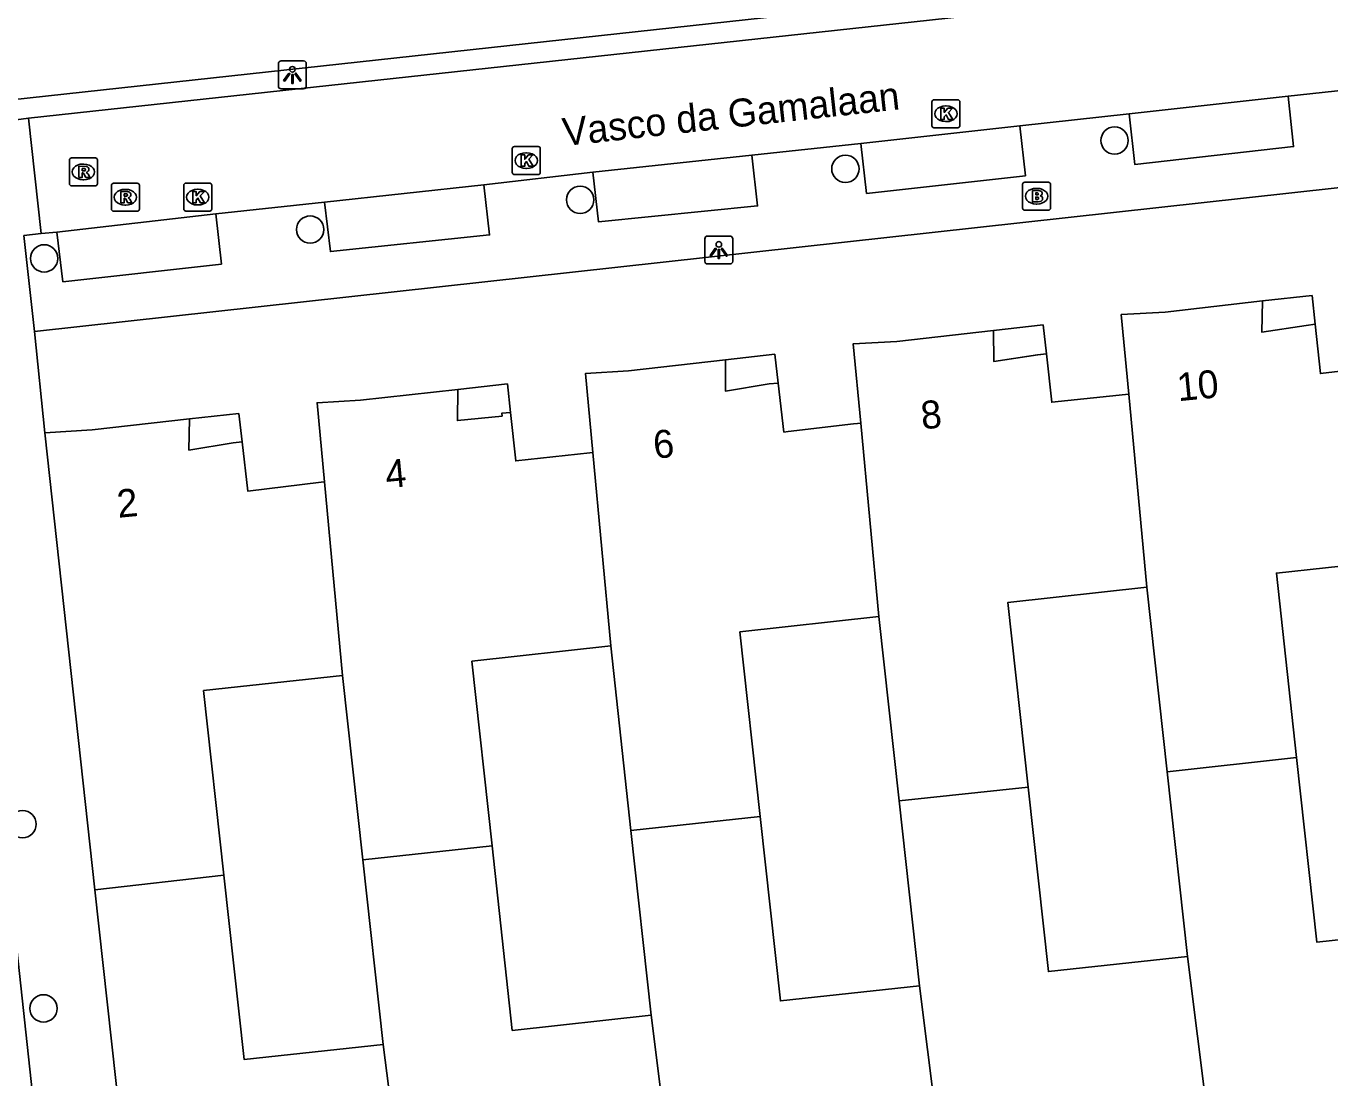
# Model space of a CAD drawing. Extents: x 161253 to 161848, y 384872 to 385383.
# Drawn here: x 161347.65 to 161394.3, y 385074.55 to 385112.17 of the extents above; entities that cross this region are included whole.
import ezdxf

# ---------------------------------------------------------------- set-up
doc = ezdxf.new("R2010")
doc.units = 0
for name, color, linetype in [('IMGEO_Boom', 7, 'Continuous'), ('IMGEO_Brandkraan', 7, 'Continuous'), ('IMGEO_Kolk', 7, 'Continuous'), ('IMGEO_Lichtpunt', 7, 'Continuous'), ('IMGEO_Openbare_ruimte_label', 7, 'Continuous'), ('IMGEO_Pand', 7, 'Continuous'), ('IMGEO_Pand_nummerreeks', 7, 'Continuous'), ('IMGEO_Pand_overbouw', 7, 'Continuous'), ('IMGEO_Rijbaan_lokaal_open', 7, 'Continuous'), ('IMGEO_Rioolput', 7, 'Continuous'), ('IMGEO_Voetpad_open', 7, 'Continuous')]:
    doc.layers.add(name, color=color, linetype=linetype)

msp = doc.modelspace()

# ---------------------------------------------------------------- linework, layer by layer
at = {"layer": 'IMGEO_Boom'}
for centre in [(161386.594, 385108.08), (161376.963, 385107.067), (161367.474, 385105.962), (161357.815, 385104.894), (161348.299, 385103.866), (161347.527, 385083.626), (161348.275, 385077.04)]:
    msp.add_circle(centre, 0.489, dxfattribs=at)
at = {"layer": 'IMGEO_Brandkraan'}
for p, q in [((161383.303, 385105.663), (161383.303, 385106.515)), ((161383.378, 385106.589), (161384.23, 385106.589)), ((161384.304, 385106.515), (161384.304, 385105.663)), ((161383.791, 385106.369), (161383.816, 385106.369)), ((161384.23, 385105.589), (161383.378, 385105.589)), ((161383.814, 385105.809), (161383.789, 385105.809))]:
    msp.add_line(p, q, dxfattribs=at)
for points in [[(161383.303, 385105.663), (161383.303, 385106.515)], [(161383.378, 385106.589), (161384.23, 385106.589)], [(161384.304, 385106.515), (161384.304, 385105.663)], [(161383.651, 385106.289), (161383.651, 385105.889), (161383.864, 385105.889)], [(161383.882, 385106.289), (161383.651, 385106.289)], [(161383.83, 385106.208), (161383.776, 385106.208), (161383.776, 385106.132)], [(161383.776, 385106.132), (161383.829, 385106.132)], [(161383.838, 385106.056), (161383.776, 385106.056), (161383.776, 385105.975)], [(161384.23, 385105.589), (161383.378, 385105.589)], [(161383.776, 385105.975), (161383.838, 385105.975)]]:
    msp.add_lwpolyline(points, dxfattribs=at)
for centre, radius, start, end in [((161383.38, 385106.513), 0.0765, 91.552, 178.448), ((161383.38, 385106.513), 0.0765, 91.552, 178.448), ((161384.228, 385106.513), 0.0765, 1.552, 88.448), ((161384.228, 385106.513), 0.0765, 1.552, 88.448), ((161383.831, 385106.17), 0.0379, 267.8285, 90.9355), ((161383.839, 385106.015), 0.0404, 269.8759, 90.5077), ((161383.886, 385106.144), 0.145, 59.4692, 91.5367), ((161383.911, 385106.191), 0.0922, 285.5137, 58.1501), ((161383.916, 385105.999), 0.105, 301.3115, 78.989), ((161383.38, 385105.665), 0.0765, 181.552, 268.448), ((161383.38, 385105.665), 0.0765, 181.552, 268.448), ((161383.87, 385106.14), 0.251, 268.6676, 293.5347), ((161384.228, 385105.665), 0.0765, 271.552, 358.448), ((161384.228, 385105.665), 0.0765, 271.552, 358.448)]:
    msp.add_arc(centre, radius, start, end, dxfattribs=at)
for centre, major_axis, ratio, start_param, end_param in [((161383.79, 385106.089), (-0.387, 0.002), 0.722429, 4.712389, 7.853982), ((161383.815, 385106.089), (-0.39, 0.002), 0.717154, 1.570796, 4.712389)]:
    msp.add_ellipse(centre, major_axis=major_axis, ratio=ratio, start_param=start_param, end_param=end_param, dxfattribs=at)
at = {"layer": 'IMGEO_Kolk'}
for p, q in [((161380.058, 385108.61), (161380.058, 385109.462)), ((161380.133, 385109.536), (161380.985, 385109.536)), ((161380.546, 385109.316), (161380.571, 385109.316)), ((161381.059, 385109.462), (161381.059, 385108.61)), ((161380.985, 385108.536), (161380.133, 385108.536)), ((161380.569, 385108.756), (161380.544, 385108.756)), ((161365.048, 385106.937), (161365.048, 385107.789)), ((161365.123, 385107.863), (161365.975, 385107.863)), ((161365.536, 385107.643), (161365.561, 385107.643)), ((161366.049, 385107.789), (161366.049, 385106.937)), ((161365.559, 385107.083), (161365.534, 385107.083)), ((161353.371, 385106.555), (161354.223, 385106.555)), ((161365.975, 385106.863), (161365.123, 385106.863)), ((161353.296, 385105.629), (161353.296, 385106.481)), ((161353.784, 385106.335), (161353.809, 385106.335)), ((161354.297, 385106.481), (161354.297, 385105.629)), ((161354.223, 385105.555), (161353.371, 385105.555)), ((161353.807, 385105.775), (161353.782, 385105.775))]:
    msp.add_line(p, q, dxfattribs=at)
for points in [[(161380.058, 385108.61), (161380.058, 385109.462)], [(161380.133, 385109.536), (161380.985, 385109.536)], [(161381.059, 385109.462), (161381.059, 385108.61)], [(161380.379, 385109.236), (161380.502, 385109.236), (161380.502, 385109.085), (161380.632, 385109.236), (161380.796, 385109.236), (161380.65, 385109.085), (161380.803, 385108.836), (161380.651, 385108.836), (161380.566, 385109), (161380.502, 385108.933), (161380.502, 385108.836), (161380.379, 385108.836), (161380.379, 385109.236)], [(161380.985, 385108.536), (161380.133, 385108.536)], [(161365.048, 385106.937), (161365.048, 385107.789)], [(161365.123, 385107.863), (161365.975, 385107.863)], [(161365.369, 385107.563), (161365.492, 385107.563), (161365.492, 385107.412), (161365.622, 385107.563), (161365.786, 385107.563), (161365.64, 385107.412), (161365.793, 385107.163), (161365.641, 385107.163), (161365.556, 385107.327), (161365.492, 385107.26), (161365.492, 385107.163), (161365.369, 385107.163), (161365.369, 385107.563)], [(161366.049, 385107.789), (161366.049, 385106.937)], [(161353.371, 385106.555), (161354.223, 385106.555)], [(161365.975, 385106.863), (161365.123, 385106.863)], [(161353.296, 385105.629), (161353.296, 385106.481)], [(161353.617, 385106.255), (161353.74, 385106.255), (161353.74, 385106.104), (161353.87, 385106.255), (161354.034, 385106.255), (161353.888, 385106.104), (161354.041, 385105.855), (161353.889, 385105.855), (161353.804, 385106.019), (161353.74, 385105.952), (161353.74, 385105.855), (161353.617, 385105.855), (161353.617, 385106.255)], [(161354.297, 385106.481), (161354.297, 385105.629)], [(161354.223, 385105.555), (161353.371, 385105.555)]]:
    msp.add_lwpolyline(points, dxfattribs=at)
for centre, start, end in [((161380.135, 385109.46), 91.552, 178.448), ((161380.135, 385109.46), 91.552, 178.448), ((161380.983, 385109.46), 1.552, 88.448), ((161380.983, 385109.46), 1.552, 88.448), ((161380.135, 385108.612), 181.552, 268.448), ((161380.135, 385108.612), 181.552, 268.448), ((161380.983, 385108.612), 271.552, 358.448), ((161380.983, 385108.612), 271.552, 358.448), ((161365.125, 385107.787), 91.552, 178.448), ((161365.125, 385107.787), 91.552, 178.448), ((161365.973, 385107.787), 1.552, 88.448), ((161365.973, 385107.787), 1.552, 88.448), ((161353.373, 385106.479), 91.552, 178.448), ((161353.373, 385106.479), 91.552, 178.448), ((161354.221, 385106.479), 1.552, 88.448), ((161354.221, 385106.479), 1.552, 88.448), ((161365.125, 385106.939), 181.552, 268.448), ((161365.125, 385106.939), 181.552, 268.448), ((161365.973, 385106.939), 271.552, 358.448), ((161365.973, 385106.939), 271.552, 358.448), ((161353.373, 385105.631), 181.552, 268.448), ((161353.373, 385105.631), 181.552, 268.448), ((161354.221, 385105.631), 271.552, 358.448), ((161354.221, 385105.631), 271.552, 358.448)]:
    msp.add_arc(centre, 0.0765, start, end, dxfattribs=at)
for centre, major_axis, ratio, start_param, end_param in [((161380.545, 385109.036), (-0.387, 0.002), 0.722429, 4.712389, 7.853982), ((161380.57, 385109.036), (-0.39, 0.002), 0.717154, 1.570796, 4.712389), ((161365.535, 385107.363), (-0.387, 0.002), 0.722429, 4.712389, 7.853982), ((161365.56, 385107.363), (-0.39, 0.002), 0.717154, 1.570796, 4.712389), ((161353.783, 385106.055), (-0.387, 0.002), 0.722429, 4.712389, 7.853982), ((161353.808, 385106.055), (-0.39, 0.002), 0.717154, 1.570796, 4.712389)]:
    msp.add_ellipse(centre, major_axis=major_axis, ratio=ratio, start_param=start_param, end_param=end_param, dxfattribs=at)
at = {"layer": 'IMGEO_Lichtpunt'}
for p, q in [((161356.682, 385110.83), (161356.682, 385110.023)), ((161356.682, 385110.83), (161356.682, 385110.023)), ((161357.584, 385110.925), (161356.776, 385110.925)), ((161357.584, 385110.925), (161356.776, 385110.925)), ((161357.678, 385110.023), (161357.678, 385110.83)), ((161357.678, 385110.023), (161357.678, 385110.83)), ((161356.776, 385109.929), (161357.584, 385109.929)), ((161356.776, 385109.929), (161357.584, 385109.929)), ((161372.838, 385104.662), (161372.03, 385104.662)), ((161372.838, 385104.662), (161372.03, 385104.662)), ((161371.936, 385104.567), (161371.936, 385103.76)), ((161371.936, 385104.567), (161371.936, 385103.76)), ((161372.932, 385103.76), (161372.932, 385104.567)), ((161372.932, 385103.76), (161372.932, 385104.567)), ((161372.03, 385103.666), (161372.838, 385103.666)), ((161372.03, 385103.666), (161372.838, 385103.666))]:
    msp.add_line(p, q, dxfattribs=at)
for points in [[(161357.056, 385110.494), (161357.095, 385110.466), (161356.907, 385110.204), (161356.869, 385110.231), (161357.056, 385110.494)], [(161357.158, 385110.446), (161357.205, 385110.446), (161357.205, 385110.124), (161357.158, 385110.124), (161357.158, 385110.446)], [(161357.268, 385110.466), (161357.306, 385110.493), (161357.493, 385110.231), (161357.454, 385110.203), (161357.268, 385110.466)], [(161372.31, 385104.231), (161372.349, 385104.203), (161372.161, 385103.941), (161372.123, 385103.968), (161372.31, 385104.231)], [(161372.412, 385104.183), (161372.459, 385104.183), (161372.459, 385103.861), (161372.412, 385103.861), (161372.412, 385104.183)], [(161372.522, 385104.203), (161372.56, 385104.23), (161372.747, 385103.968), (161372.708, 385103.94), (161372.522, 385104.203)]]:
    msp.add_lwpolyline(points, dxfattribs=at)
for centre in [(161357.181, 385110.628), (161372.435, 385104.365)]:
    msp.add_circle(centre, 0.0994, dxfattribs=at)
for centre, start, end in [((161356.776, 385110.83), 90, 180), ((161356.776, 385110.83), 90, 180), ((161357.584, 385110.83), 0, 90), ((161357.584, 385110.83), 0, 90), ((161356.776, 385110.023), 180, 270), ((161356.776, 385110.023), 180, 270), ((161357.584, 385110.023), 270, 0), ((161357.584, 385110.023), 270, 360), ((161372.03, 385104.567), 90, 180), ((161372.03, 385104.567), 90, 180), ((161372.838, 385104.567), 0, 90), ((161372.838, 385104.567), 0, 90), ((161372.03, 385103.76), 180, 270), ((161372.03, 385103.76), 180, 270), ((161372.838, 385103.76), 270, 0), ((161372.838, 385103.76), 270, 360)]:
    msp.add_arc(centre, 0.0946, start, end, dxfattribs=at)
at = {"layer": 'IMGEO_Pand'}
for points in [[(161396.893, 385100.095), (161393.957, 385099.746), (161393.768, 385101.507), (161393.446, 385101.462), (161391.863, 385101.222), (161391.885, 385102.341), (161388.402, 385101.946), (161386.833, 385101.856), (161387.099, 385099.013)], [(161377.511, 385097.974), (161377.246, 385100.811), (161378.806, 385100.893), (161382.257, 385101.285), (161382.274, 385100.174), (161383.835, 385100.418), (161384.156, 385100.449), (161384.347, 385098.716), (161386.986, 385099.001), (161387.099, 385099.013)], [(161377.511, 385097.974), (161377.398, 385097.961), (161377.249, 385097.943), (161374.919, 385097.667), (161374.763, 385097.649), (161374.563, 385099.398), (161374.239, 385099.377), (161372.674, 385099.12), (161372.675, 385100.219), (161372.675, 385100.238), (161369.2, 385099.839), (161367.668, 385099.753), (161367.93, 385096.926)], [(161367.93, 385096.926), (161367.817, 385096.913), (161365.171, 385096.619), (161364.982, 385098.356), (161364.67, 385098.325), (161364.68, 385098.223), (161363.085, 385098.066), (161363.102, 385099.18), (161359.617, 385098.791), (161358.064, 385098.701), (161358.329, 385095.868)], [(161387.099, 385099.013), (161387.745, 385092.1)], [(161358.329, 385095.868), (161358.216, 385095.855), (161355.582, 385095.542), (161355.384, 385097.3), (161355.064, 385097.262), (161353.479, 385097.007), (161353.505, 385098.125), (161350.02, 385097.735), (161348.324, 385097.628)], [(161348.324, 385097.628), (161350.119, 385081.284)], [(161378.158, 385091.05), (161377.511, 385097.974)], [(161367.93, 385096.926), (161368.572, 385090.002)], [(161358.329, 385095.868), (161358.976, 385088.951)], [(161393.106, 385086.007), (161392.383, 385092.607), (161397.643, 385093.177)], [(161383.499, 385084.956), (161382.774, 385091.556), (161387.745, 385092.1)], [(161387.745, 385092.1), (161388.471, 385085.497)], [(161373.914, 385083.906), (161373.188, 385090.506), (161378.158, 385091.05)], [(161378.158, 385091.05), (161378.883, 385084.458)], [(161364.324, 385082.857), (161363.603, 385089.458), (161368.572, 385090.002)], [(161368.572, 385090.002), (161369.294, 385083.399)], [(161354.733, 385081.808), (161354.006, 385088.408), (161358.976, 385088.951)], [(161358.976, 385088.951), (161359.704, 385082.348)], [(161388.471, 385085.497), (161393.106, 385086.007)], [(161399.089, 385079.976), (161393.83, 385079.404), (161393.106, 385086.007)], [(161388.471, 385085.497), (161389.196, 385078.897)], [(161383.499, 385084.956), (161378.883, 385084.458)], [(161389.196, 385078.897), (161384.225, 385078.353), (161383.499, 385084.956)], [(161378.883, 385084.458), (161379.61, 385077.848)], [(161369.294, 385083.399), (161373.914, 385083.906)], [(161379.61, 385077.848), (161374.64, 385077.304), (161373.914, 385083.906)], [(161369.294, 385083.399), (161370.015, 385076.798)], [(161364.324, 385082.857), (161359.704, 385082.348)], [(161370.015, 385076.798), (161365.046, 385076.254), (161364.324, 385082.857)], [(161359.704, 385082.348), (161360.431, 385075.749)], [(161354.733, 385081.808), (161350.119, 385081.284)], [(161360.431, 385075.749), (161355.46, 385075.205), (161354.733, 385081.808)], [(161350.119, 385081.284), (161351.915, 385064.931)], [(161390.289, 385070.246), (161389.196, 385078.897)], [(161379.61, 385077.848), (161380.486, 385070.921)], [(161371.106, 385068.129), (161370.015, 385076.798)], [(161361.306, 385068.843), (161360.431, 385075.749)]]:
    msp.add_lwpolyline(points, dxfattribs=at)
at = {"layer": 'IMGEO_Pand_overbouw'}
for points in [[(161393.657, 385102.542), (161391.885, 385102.341), (161391.863, 385101.222), (161393.446, 385101.462), (161393.768, 385101.507)], [(161384.041, 385101.488), (161382.257, 385101.285), (161382.274, 385100.174), (161383.849, 385100.419), (161384.156, 385100.449)], [(161374.444, 385100.441), (161372.675, 385100.238), (161372.674, 385099.12), (161374.239, 385099.377), (161374.563, 385099.398)], [(161364.871, 385099.377), (161363.102, 385099.18), (161363.085, 385098.066), (161364.68, 385098.223), (161364.67, 385098.325), (161364.982, 385098.356)], [(161355.269, 385098.322), (161353.505, 385098.125), (161353.479, 385097.007), (161355.064, 385097.262), (161355.384, 385097.3)]]:
    msp.add_lwpolyline(points, close=True, dxfattribs=at)
at = {"layer": 'IMGEO_Rijbaan_lokaal_open'}
for points in [[(161347.74, 385108.882), (161395.323, 385114.062)], [(161395.787, 385109.99), (161392.803, 385109.668)], [(161387.116, 385109.034), (161392.803, 385109.668)], [(161347.116, 385108.799), (161347.74, 385108.882)], [(161347.74, 385108.882), (161348.197, 385104.749)], [(161387.116, 385109.034), (161383.208, 385108.61)], [(161377.519, 385107.972), (161383.208, 385108.61)], [(161377.519, 385107.972), (161373.62, 385107.557)], [(161367.933, 385106.944), (161373.62, 385107.557)], [(161358.333, 385105.878), (161364.034, 385106.491)], [(161367.933, 385106.944), (161364.034, 385106.491)], [(161358.333, 385105.878), (161354.446, 385105.455)], [(161348.755, 385104.797), (161354.446, 385105.455)], [(161348.197, 385104.749), (161347.569, 385104.681)], [(161348.755, 385104.797), (161348.197, 385104.749)], [(161345.081, 385099.589), (161346.704, 385084.797), (161348.495, 385068.357), (161350.213, 385052.904), (161350.244, 385052.658), (161350.335, 385052.113), (161350.474, 385051.578), (161350.661, 385051.057), (161350.893, 385050.555), (161351.17, 385050.076), (161351.488, 385049.624), (161351.845, 385049.202), (161352.238, 385048.813), (161352.665, 385048.461), (161353.121, 385048.149), (161353.603, 385047.878), (161354.108, 385047.652), (161354.63, 385047.472), (161355.167, 385047.339), (161355.714, 385047.255), (161356.265, 385047.219), (161356.818, 385047.234), (161357.367, 385047.297), (161357.909, 385047.41)]]:
    msp.add_lwpolyline(points, dxfattribs=at)
at = {"layer": 'IMGEO_Rioolput'}
for p, q in [((161349.28, 385107.459), (161350.132, 385107.459)), ((161349.205, 385106.533), (161349.205, 385107.385)), ((161349.693, 385107.239), (161349.718, 385107.239)), ((161350.206, 385107.385), (161350.206, 385106.533)), ((161349.716, 385106.679), (161349.691, 385106.679)), ((161350.782, 385106.553), (161351.634, 385106.553)), ((161350.132, 385106.459), (161349.28, 385106.459)), ((161350.707, 385105.627), (161350.707, 385106.479)), ((161351.195, 385106.333), (161351.22, 385106.333)), ((161351.708, 385106.479), (161351.708, 385105.627)), ((161351.634, 385105.553), (161350.782, 385105.553)), ((161351.218, 385105.773), (161351.193, 385105.773))]:
    msp.add_line(p, q, dxfattribs=at)
for points in [[(161349.28, 385107.459), (161350.132, 385107.459)], [(161349.205, 385106.533), (161349.205, 385107.385)], [(161349.794, 385107.157), (161349.542, 385107.159), (161349.542, 385106.759)], [(161349.72, 385107.078), (161349.666, 385107.078), (161349.666, 385106.997)], [(161349.666, 385106.997), (161349.718, 385106.997)], [(161350.206, 385107.385), (161350.206, 385106.533)], [(161349.542, 385106.759), (161349.666, 385106.759), (161349.666, 385106.921), (161349.677, 385106.921)], [(161349.724, 385106.892), (161349.795, 385106.759), (161349.935, 385106.759), (161349.87, 385106.885)], [(161350.782, 385106.553), (161351.634, 385106.553)], [(161350.132, 385106.459), (161349.28, 385106.459)], [(161350.707, 385105.627), (161350.707, 385106.479)], [(161351.296, 385106.251), (161351.044, 385106.253), (161351.044, 385105.853)], [(161351.222, 385106.172), (161351.168, 385106.172), (161351.168, 385106.091)], [(161351.168, 385106.091), (161351.22, 385106.091)], [(161351.708, 385106.479), (161351.708, 385105.627)], [(161351.634, 385105.553), (161350.782, 385105.553)], [(161351.044, 385105.853), (161351.168, 385105.853), (161351.168, 385106.015), (161351.179, 385106.015)], [(161351.226, 385105.986), (161351.297, 385105.853), (161351.437, 385105.853), (161351.372, 385105.979)]]:
    msp.add_lwpolyline(points, dxfattribs=at)
for centre, radius, start, end in [((161349.282, 385107.383), 0.0765, 91.552, 178.448), ((161349.282, 385107.383), 0.0765, 91.552, 178.448), ((161350.13, 385107.383), 0.0765, 1.552, 88.448), ((161350.13, 385107.383), 0.0765, 1.552, 88.448), ((161349.702, 385107.186), 0.19, 274.7715, 282.9687), ((161349.726, 385106.982), 0.0964, 77.0061, 93.1865), ((161349.74, 385107.039), 0.0378, 276.6634, 79.6772), ((161349.793, 385107.047), 0.109, 350.3612, 89.416), ((161349.791, 385107.047), 0.112, 277.5842, 350.9817), ((161349.282, 385106.535), 0.0765, 181.552, 268.448), ((161349.282, 385106.535), 0.0765, 181.552, 268.448), ((161349.676, 385106.868), 0.0533, 26.0293, 88.6989), ((161349.775, 385106.832), 0.108, 29.5134, 73.7905), ((161350.13, 385106.535), 0.0765, 271.552, 358.448), ((161350.13, 385106.535), 0.0765, 271.552, 358.448), ((161350.784, 385106.477), 0.0765, 91.552, 178.448), ((161350.784, 385106.477), 0.0765, 91.552, 178.448), ((161351.632, 385106.477), 0.0765, 1.552, 88.448), ((161351.632, 385106.477), 0.0765, 1.552, 88.448), ((161351.204, 385106.28), 0.19, 274.7715, 282.9687), ((161351.228, 385106.076), 0.0964, 77.0061, 93.1865), ((161351.242, 385106.133), 0.0378, 276.6634, 79.6772), ((161351.295, 385106.141), 0.109, 350.3612, 89.416), ((161351.293, 385106.141), 0.112, 277.5842, 350.9817), ((161351.277, 385105.926), 0.108, 29.5134, 73.7905), ((161350.784, 385105.629), 0.0765, 181.552, 268.448), ((161350.784, 385105.629), 0.0765, 181.552, 268.448), ((161351.178, 385105.962), 0.0533, 26.0293, 88.6989), ((161351.632, 385105.629), 0.0765, 271.552, 358.448), ((161351.632, 385105.629), 0.0765, 271.552, 358.448)]:
    msp.add_arc(centre, radius, start, end, dxfattribs=at)
for centre, major_axis, ratio, start_param, end_param in [((161349.692, 385106.959), (-0.387, 0.002), 0.722429, 4.712389, 7.853982), ((161349.717, 385106.959), (-0.39, 0.002), 0.717154, 1.570796, 4.712389), ((161351.194, 385106.053), (-0.387, 0.002), 0.722429, 4.712389, 7.853982), ((161351.219, 385106.053), (-0.39, 0.002), 0.717154, 1.570796, 4.712389)]:
    msp.add_ellipse(centre, major_axis=major_axis, ratio=ratio, start_param=start_param, end_param=end_param, dxfattribs=at)
at = {"layer": 'IMGEO_Voetpad_open'}
for points in [[(161395.24, 385114.796), (161347.043, 385109.527)], [(161392.803, 385109.668), (161392.995, 385107.862), (161387.313, 385107.226), (161387.116, 385109.034)], [(161383.208, 385108.61), (161383.406, 385106.819), (161377.721, 385106.189), (161377.519, 385107.972)], [(161373.62, 385107.557), (161373.825, 385105.741), (161368.134, 385105.166), (161367.933, 385106.944)], [(161396.177, 385106.561), (161347.958, 385101.247)], [(161364.034, 385106.491), (161364.238, 385104.702), (161358.539, 385104.107), (161358.333, 385105.878)], [(161354.446, 385105.455), (161354.642, 385103.658), (161348.975, 385103.03), (161348.755, 385104.797)], [(161347.958, 385101.247), (161347.569, 385104.681)], [(161347.958, 385101.247), (161348.324, 385097.628)]]:
    msp.add_lwpolyline(points, dxfattribs=at)

# ---------------------------------------------------------------- texts
at = {"layer": 'IMGEO_Openbare_ruimte_label'}
msp.add_text('Vasco da Gamalaan', height=1, rotation=6.2579, dxfattribs=at).set_placement((161366.899, 385107.879))
at = {"layer": 'IMGEO_Pand_nummerreeks'}
for s, rotation, p in [('10', 5.5061, (161388.872, 385098.755)), ('8', 5.4316, (161379.709, 385097.748)), ('6', 5.552, (161370.136, 385096.696)), ('4', 5.4546, (161360.552, 385095.642)), ('2', 5.4775, (161350.951, 385094.584))]:
    msp.add_text(s, height=1, rotation=rotation, dxfattribs=at).set_placement(p)

doc.saveas('drawing.dxf')
